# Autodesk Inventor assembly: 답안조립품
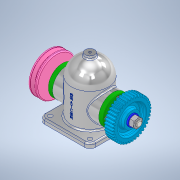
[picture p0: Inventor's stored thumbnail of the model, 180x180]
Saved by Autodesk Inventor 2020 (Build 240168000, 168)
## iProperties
Created: 2021-07
Part Number: 답안조립품
Document SubType Name: Assembly
Designer: Owner
Author: Owner
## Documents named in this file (14)
- C:\Users\Owner\Desktop\710716V1009\답안조립품.iam
- C:\Users\Owner\Desktop\710716V1009\본체.ipt
- C:\Users\Owner\Desktop\710716V1009\V-벨트풀리.ipt
- V-벨트풀리.ipt
- C:\Users\Owner\Desktop\710716V1009\너트 M12x1.25.ipt
- C:\Users\Owner\Desktop\710716V1009\베어링 6203.ipt
- C:\Users\Owner\Desktop\710716V1009\볼트 M4.ipt
- C:\Users\Owner\Desktop\710716V1009\부시.ipt
- C:\Users\Owner\Desktop\710716V1009\스퍼기어.ipt
- C:\Users\Owner\Desktop\710716V1009\오일 실 26 38 8.ipt
- C:\Users\Owner\Desktop\710716V1009\와셔 12x24.ipt
- C:\Users\Owner\Desktop\710716V1009\축.ipt
- C:\Users\Owner\Desktop\710716V1009\커버.ipt
- C:\Users\Owner\Desktop\710716V1009\키 5x5x12.ipt
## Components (1 placed, 1 different names)
1. V-벨트풀리:1
